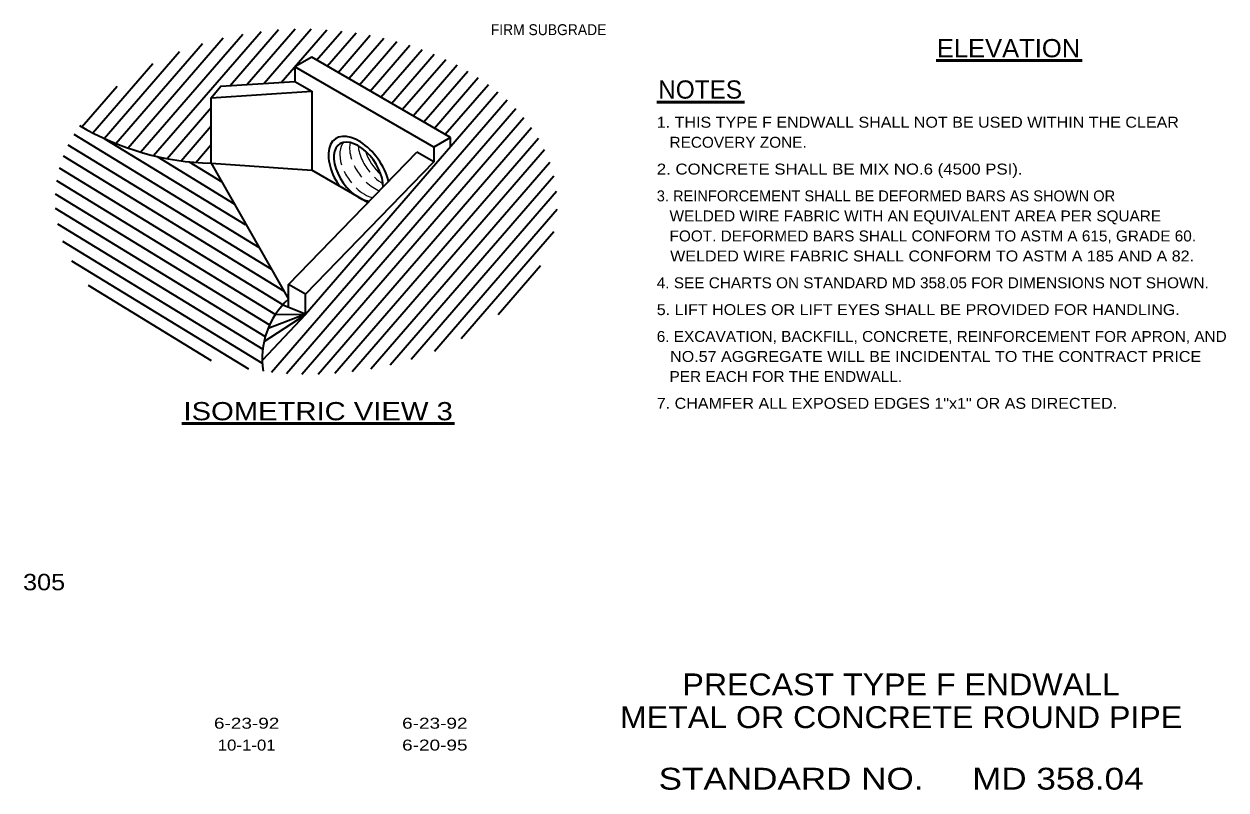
# Model space of a CAD drawing. Extents: x 178962.5 to 178977.5, y 178951.2 to 178972.9.
# Drawn here: x 178962.51 to 178977.37, y 178951.22 to 178960.68 of the extents above; entities that cross this region are included whole.
import ezdxf
from ezdxf.enums import TextEntityAlignment as Align

# ---------------------------------------------------------------- set-up
doc = ezdxf.new("R2010")
doc.units = 0
doc.header["$LTSCALE"] = 0.054
for name, color, linetype, lineweight in [('1', 7, 'Continuous', 35), ('12', 7, 'Continuous', 53), ('13', 7, 'Continuous', 53), ('6', 7, 'Continuous', 13)]:
    doc.layers.add(name, color=color, linetype=linetype, lineweight=lineweight)

msp = doc.modelspace()

# ---------------------------------------------------------------- linework, layer by layer
at = {"layer": '1'}
for p, q in [((178963.94767, 178959.09992), (178965.21108, 178960.55833)), ((178964.10858, 178959.05633), (178965.43792, 178960.59075)), ((178965.65375, 178960.61058), (178965.05558, 178959.92017)), ((178965.86025, 178960.61967), (178965.26583, 178959.93342)), ((178966.05875, 178960.61942), (178965.47617, 178959.94692)), ((178965.6865, 178959.96025), (178966.25017, 178960.611)), ((178966.12475, 178960.23683), (178966.435, 178960.595)), ((178966.25717, 178960.16042), (178966.61392, 178960.57225)), ((178966.38967, 178960.08383), (178966.78725, 178960.54292)), ((178963.64292, 178959.20667), (178964.71242, 178960.44133)), ((178963.79258, 178959.15017), (178964.97058, 178960.51008)), ((178966.52208, 178960.00742), (178966.95525, 178960.50742)), ((178966.65458, 178959.93083), (178967.11808, 178960.46617)), ((178966.787, 178959.8545), (178967.276, 178960.41917)), ((178966.9195, 178959.77792), (178967.42942, 178960.36667)), ((178963.49833, 178959.26908), (178964.42858, 178960.343)), ((178967.05192, 178959.70158), (178967.57783, 178960.30858)), ((178967.18442, 178959.62508), (178967.7215, 178960.24517)), ((178963.35875, 178959.33742), (178964.10142, 178960.19475)), ((178967.5735, 178959.16008), (178965.85658, 178960.15133)), ((178967.31683, 178959.54858), (178967.8605, 178960.17617)), ((178967.44925, 178959.47217), (178967.99458, 178960.10175)), ((178967.58183, 178959.39558), (178968.12383, 178960.0215)), ((178967.71417, 178959.31917), (178968.248, 178959.93542)), ((178963.22408, 178959.41108), (178963.65925, 178959.91375)), ((178964.82308, 178959.77183), (178966.06475, 178959.85092)), ((178964.82308, 178958.96083), (178964.82308, 178959.77183)), ((178965.98675, 178957.09517), (178968.36675, 178959.84325)), ((178966.06475, 178959.85092), (178966.06475, 178958.87817)), ((178964.27575, 178959.01983), (178964.82308, 178959.65167)), ((178965.56642, 178956.3805), (178968.48, 178959.7445)), ((178965.75183, 178956.365), (178968.58717, 178959.63892)), ((178965.94367, 178956.35708), (178968.68775, 178959.52567)), ((178963.12242, 178959.32292), (178965.4145, 178957.92217)), ((178964.44967, 178958.99125), (178964.82308, 178959.42225)), ((178966.1425, 178956.3575), (178968.78125, 178959.40425)), ((178963.05058, 178959.19092), (178965.56817, 178957.65233)), ((178963.49833, 178959.26908), (178965.2405, 178958.20458)), ((178964.63108, 178958.97125), (178964.82308, 178959.19283)), ((178966.34967, 178956.36725), (178968.86675, 178959.27342)), ((178967.78167, 178959.16758), (178967.78167, 178959.28033)), ((178962.99017, 178959.05167), (178965.72183, 178957.38225)), ((178964.1515, 178959.04608), (178965.107, 178958.46208)), ((178965.77867, 178957.463), (178967.36542, 178959.1)), ((178966.56617, 178956.38775), (178968.94258, 178959.13167)), ((178962.9425, 178958.90492), (178965.70967, 178957.21383)), ((178964.54917, 178958.97908), (178964.95325, 178958.732)), ((178964.82308, 178958.96083), (178965.77867, 178957.28275)), ((178964.82308, 178958.96083), (178966.06475, 178958.87817)), ((178966.75792, 178958.47792), (178966.06475, 178958.87817)), ((178966.79367, 178956.421), (178969.0075, 178958.97717)), ((178962.90883, 178958.74933), (178965.61692, 178957.0945)), ((178967.035, 178956.47042), (178969.05858, 178958.80675)), ((178962.89183, 178958.58383), (178965.54358, 178956.96325)), ((178967.29467, 178956.54067), (178969.0915, 178958.61542)), ((178962.89425, 178958.40625), (178965.49017, 178956.82)), ((178967.58067, 178956.6415), (178969.09808, 178958.39358)), ((178962.92142, 178958.21367), (178965.4585, 178956.66333)), ((178962.98183, 178958.00083), (178965.45258, 178956.49092)), ((178967.91158, 178956.79433), (178969.0595, 178958.11967)), ((178963.09233, 178957.75725), (178965.281, 178956.41983)), ((178968.3705, 178957.09475), (178968.89292, 178957.69783)), ((178963.29858, 178957.45508), (178964.8205, 178956.52517)), ((178965.98675, 178957.34292), (178965.77867, 178957.463)), ((178965.77867, 178957.18117), (178965.77867, 178957.463)), ((178965.98675, 178957.09517), (178965.98675, 178957.34292)), ((178965.98675, 178957.09517), (178965.70833, 178957.21017)), ((178965.98592, 178957.09208), (178965.45575, 178956.52967)), ((178965.97967, 178957.08592), (178965.47142, 178956.75333)), ((178965.97967, 178957.09208), (178965.52425, 178956.91792)), ((178965.98283, 178957.09208), (178965.61475, 178957.08892))]:
    msp.add_line(p, q, dxfattribs=at)
for points in [[(178967.78167, 178959.28033), (178966.06475, 178960.2715), (178965.85658, 178960.15133), (178965.85658, 178959.97117), (178966.06475, 178959.85092)], [(178964.82308, 178959.77183), (178964.94008, 178959.91267), (178965.85658, 178959.97117)], [(178967.78167, 178959.28033), (178967.5735, 178959.16008), (178967.5735, 178958.97992)], [(178965.98675, 178957.34292), (178967.5735, 178958.97992), (178967.36542, 178959.1)]]:
    msp.add_lwpolyline(points, dxfattribs=at)
for centre, radius, start, end in [((178964.91007, 178962.33395), 3.37425, 239.39309, 268.52264), ((178966.4495, 178956.54352), 0.99831, 132.22474, 188.68196)]:
    msp.add_arc(centre, radius, start, end, dxfattribs=at)
for centre, major_axis, start_param, end_param in [((178966.64993, 178958.83975), (-0.29405, 0.42336), 4.11085834, 7.83395485), ((178966.64217, 178958.8583), (-0.23546, 0.339), 3.7848784, 9.00279114)]:
    msp.add_ellipse(centre, major_axis=major_axis, ratio=0.565771, start_param=start_param, end_param=end_param, dxfattribs=at)
at = {"layer": '12'}
for p, q in [((178973.78567, 178960.22958), (178975.58933, 178960.22958)), ((178964.4565, 178955.744), (178967.83092, 178955.744))]:
    msp.add_line(p, q, dxfattribs=at)
at = {"layer": '13'}
msp.add_line((178970.33, 178959.71867), (178971.414, 178959.71867), dxfattribs=at)
at = {"layer": '6'}
for centre, start_param, end_param in [((178966.71483, 178958.89621), 0.10092851, 1.07193881), ((178966.83597, 178958.97208), 0.50343363, 1.08576351), ((178966.93981, 178959.03069), 0.79189059, 1.29365142), ((178967.00901, 178959.06862), 1.06712494, 1.96482191), ((178966.83597, 178958.97208), 1.29656302, 1.71513355), ((178966.93981, 178959.03069), 1.29365147, 1.71224537), ((178966.71483, 178958.89621), 1.28373499, 1.70243585), ((178966.83597, 178958.97208), 1.92429022, 2.47710392), ((178966.93981, 178959.03069), 1.92121219, 2.26904492), ((178966.71483, 178958.89621), 1.91077405, 2.60572392)]:
    msp.add_ellipse(centre, major_axis=(-0.23546, 0.339), ratio=0.565771, start_param=start_param, end_param=end_param, dxfattribs=at)

# ---------------------------------------------------------------- texts
at = {"layer": '12', "width": 0.95}
msp.add_text('FIRM SUBGRADE', height=0.135, dxfattribs=at).set_placement((178968.27775, 178960.54492))
at = {"layer": '12'}
for s, width, p in [('ELEVATION', 1.05, (178974.67846, 178960.27142)), ('ISOMETRIC VIEW 3', 1.2, (178966.14362, 178955.78583))]:
    msp.add_text(s, height=0.225, dxfattribs=dict(at, width=width)).set_placement(p, align=Align.CENTER)
at = {"layer": '13'}
msp.add_text('NOTES', height=0.225, dxfattribs=at).set_placement((178970.86621, 178959.7605), align=Align.CENTER)
for s, width, p in [('1. THIS TYPE F ENDWALL SHALL NOT BE USED WITHIN THE CLEAR', 1.1, (178970.33, 178959.40117)), ('   RECOVERY ZONE.', 1.05, (178970.33, 178959.15367)), ('2. CONCRETE SHALL BE MIX NO.6 (4500 PSI).', 1.15, (178970.33, 178958.82225)), ('   WELDED WIRE FABRIC WITH AN EQUIVALENT AREA PER SQUARE', 1.05, (178970.33, 178958.24333)), ('   FOOT. DEFORMED BARS SHALL CONFORM TO ASTM A 615, GRADE 60.', 1.05, (178970.33, 178957.99583)), ('   WELDED WIRE FABRIC SHALL CONFORM TO ASTM A 185 AND A 82.', 1.1, (178970.33, 178957.74833)), ('4. SEE CHARTS ON STANDARD MD 358.05 FOR DIMENSIONS NOT SHOWN.', 1.05, (178970.33, 178957.41692)), ('5. LIFT HOLES OR LIFT EYES SHALL BE PROVIDED FOR HANDLING.', 1.1, (178970.33, 178957.0855)), ('6. EXCAVATION, BACKFILL, CONCRETE, REINFORCEMENT FOR APRON, AND', 1.05, (178970.33, 178956.75408)), ('   NO.57 AGGREGATE WILL BE INCIDENTAL TO THE CONTRACT PRICE', 1.1, (178970.33, 178956.50658)), ('   PER EACH FOR THE ENDWALL.', 1.05, (178970.33, 178956.25908)), ('7. CHAMFER ALL EXPOSED EDGES 1"x1" OR AS DIRECTED.', 1.1, (178970.33, 178955.92767))]:
    msp.add_text(s, height=0.135, dxfattribs=dict(at, width=width)).set_placement(p)
msp.add_text('3. REINFORCEMENT SHALL BE DEFORMED BARS AS SHOWN OR', height=0.135, dxfattribs=at).set_placement((178970.33, 178958.49083))
at = {"layer": '13', "width": 1.15}
msp.add_text('305', height=0.2025, dxfattribs=at).set_placement((178963.01533, 178953.68508), align=Align.RIGHT)
at = {"layer": '13'}
for s, height, width, p in [('PRECAST TYPE F ENDWALL', 0.27, 1.1, (178973.35088, 178952.38708)), ('METAL OR CONCRETE ROUND PIPE', 0.27, 1.1, (178973.35083, 178951.98208)), ('6-23-92', 0.135, 1.3, (178965.25996, 178951.97467)), ('6-23-92', 0.135, 1.3, (178967.58613, 178951.97467)), ('10-1-01', 0.135, 1.15, (178965.25996, 178951.70467)), ('6-20-95', 0.135, 1.3, (178967.58613, 178951.70467)), ('STANDARD NO.     MD 358.04', 0.27, 1.2, (178973.35083, 178951.22158))]:
    msp.add_text(s, height=height, dxfattribs=dict(at, width=width)).set_placement(p, align=Align.CENTER)

doc.saveas('drawing.dxf')
